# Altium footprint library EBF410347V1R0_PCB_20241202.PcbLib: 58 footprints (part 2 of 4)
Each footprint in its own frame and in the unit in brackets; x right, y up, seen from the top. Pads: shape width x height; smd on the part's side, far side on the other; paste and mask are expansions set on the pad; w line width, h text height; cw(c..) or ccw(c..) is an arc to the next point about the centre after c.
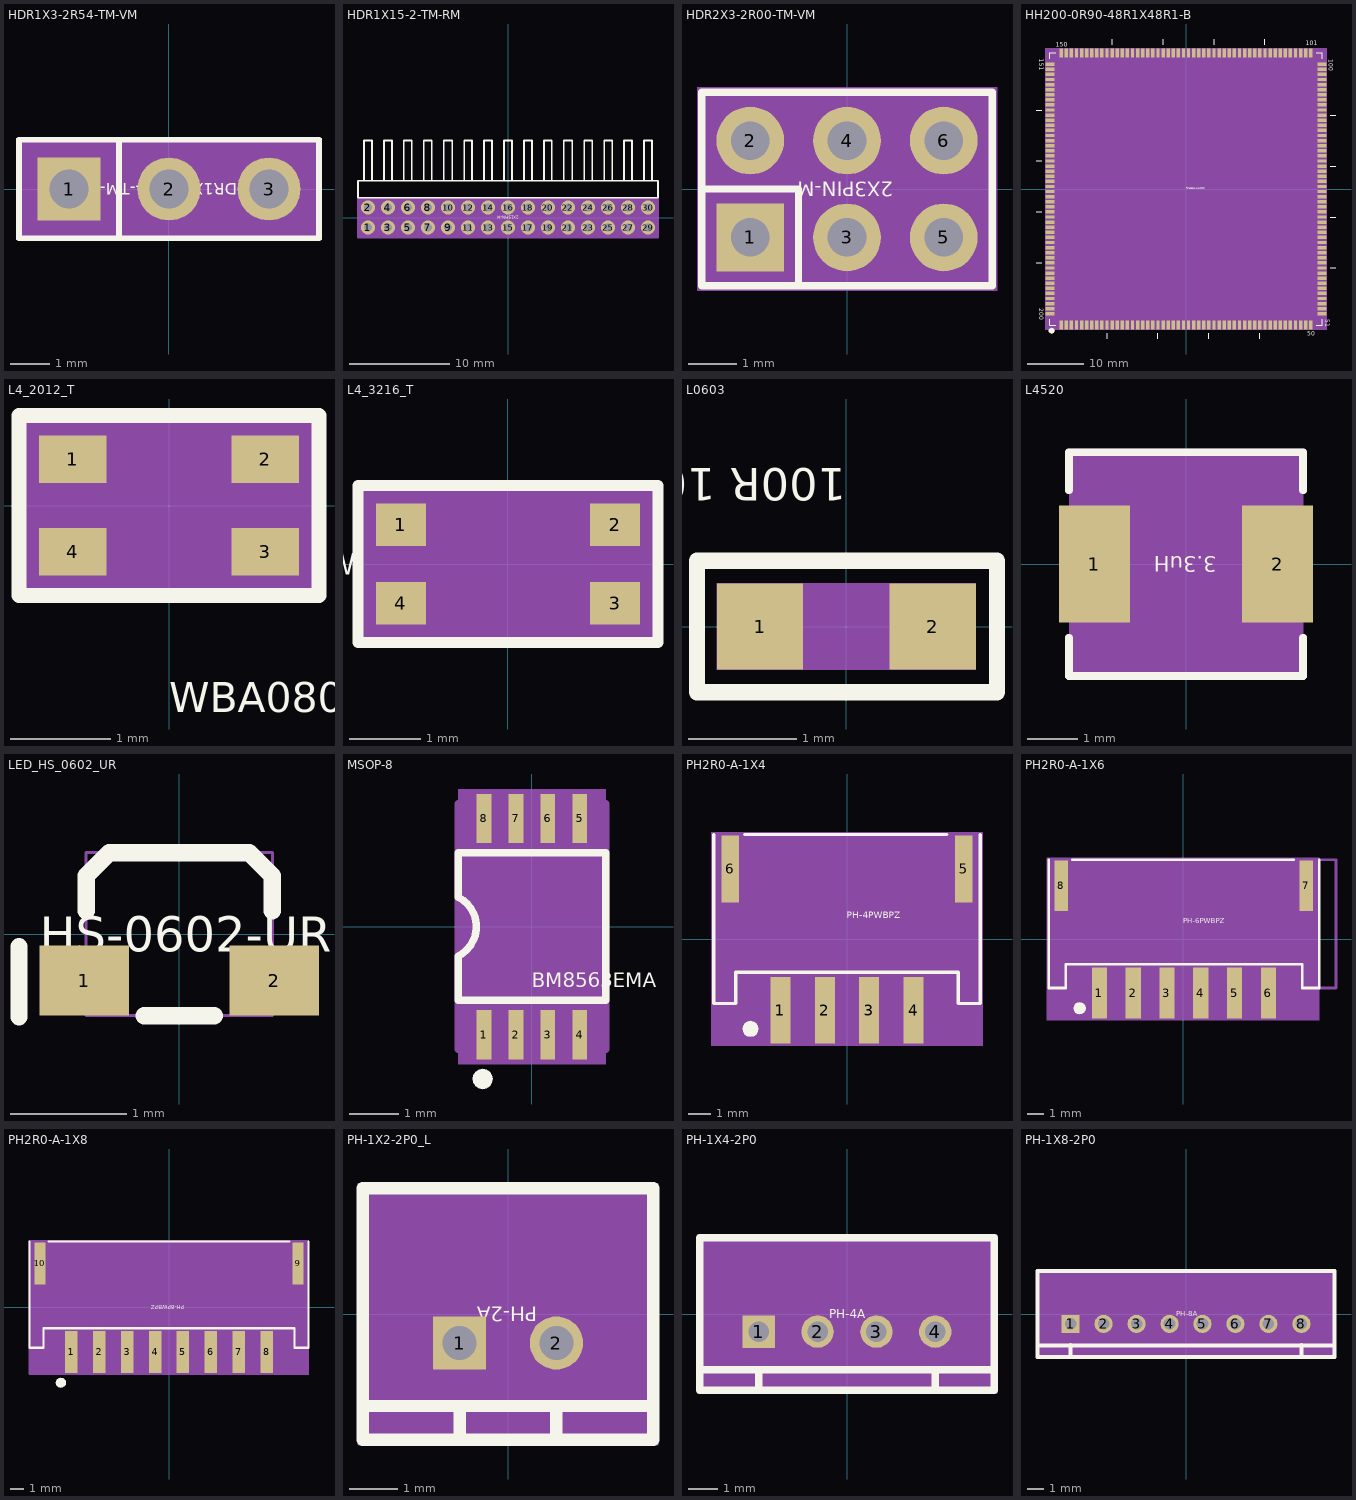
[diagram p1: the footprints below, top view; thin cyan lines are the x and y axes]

## HDR1X3-2R54-TM-VM [mm] "HDR1X3-2R54-TM-VM"
pads (3):
  rect 1.6x1.6 hole 1: 1(-2.535,0)
  round 1.6 hole 1: 2(0.005,0) 3(2.545,0)
Top Overlay:
  lines w0.15: -1.265,-1.25 -1.265,1.25 ; -1.265,1.25 3.815,1.25 3.815,-1.25 -3.805,-1.25 -3.805,1.25 -1.265,1.25
  text "HDR1X3-2R54-TM-VM" at 2.04,0.15 h0.3
Bottom Overlay:
  lines w0.5: -1.265,-0.6 -1.265,0.6 ; 1.275,-0.6 1.275,0.6
Top 3D Body:
  region: -3.805,1.25 -3.805,-1.25 3.805,-1.25 3.805,1.25
Mechanical 14:
  text "3" at 2.799,0 h0.64
  text "2" at 0.259,0 h0.64
  text "1" at -2.281,0 h0.64
Top Assembly:
  lines w0.15: -3.805,-1.25 3.815,-1.25 3.815,1.25 -3.805,1.25 -3.805,-1.25
3D body: height 3.81, standoff 0, extent -3.805,-1.25 3.805,1.25

## HDR1X15-2-TM-RM [mm] "HDR1X15-2-TM-RM"
pads (30):
  round 1.4 hole 0.8: 1(-14,-1) 2(-14,1) 3(-12,-1) 4(-12,1) 5(-10,-1) 6(-10,1) 7(-8,-1) 8(-8,1) 9(-6,-1) 10(-6,1) 11(-4,-1) 12(-4,1) 13(-2,-1) 14(-2,1) 15(0,-1) 16(0,1) 17(2,-1) 18(2,1) 19(4,-1) 20(4,1) 21(6,-1) 22(6,1) 23(8,-1) 24(8,1) 25(10,-1) 26(10,1) 27(12,-1) 28(12,1) 29(14,-1) 30(14,1)
Top Overlay:
  lines w0.15: -14.4,3.7 -14.4,7.7 -13.6,7.7 -13.6,3.7 ; -12.4,3.7 -12.4,7.7 -11.6,7.7 -11.6,3.7 ; -10.4,3.7 -10.4,7.7 -9.6,7.7 -9.6,3.7 ; -8.4,3.7 -8.4,7.7 -7.6,7.7 -7.6,3.7 ; -6.4,3.7 -6.4,7.7 -5.6,7.7 -5.6,3.7 ; -4.4,3.7 -4.4,7.7 -3.6,7.7 -3.6,3.7 ; -2.4,3.7 -2.4,7.7 -1.6,7.7 -1.6,3.7 ; -0.4,3.7 -0.4,7.7 0.4,7.7 0.4,3.7 ; 1.6,3.7 1.6,7.7 2.4,7.7 2.4,3.7 ; 3.6,3.7 3.6,7.7 4.4,7.7 4.4,3.7 ; 5.6,3.7 5.6,7.7 6.4,7.7 6.4,3.7 ; 7.6,3.7 7.6,7.7 8.4,7.7 8.4,3.7 ; 9.6,3.7 9.6,7.7 10.4,7.7 10.4,3.7 ; 11.6,3.7 11.6,7.7 12.4,7.7 12.4,3.7 ; 13.6,3.7 13.6,7.7 14.4,7.7 14.4,3.7 ; -15,2 -15,3.7 15,3.7 15,2 -15,2
  text "2X15PIN-M" at 1.08,0.15 h0.3
Bottom Overlay:
  lines w0.5: -14.6,0 14.6,0 ; -13,-1.5 -13,1.5 ; -11,-1.5 -11,1.5 ; -9,-1.5 -9,1.5 ; -7,-1.5 -7,1.5 ; -5,-1.5 -5,1.5 ; -3,-1.5 -3,1.5 ; -1,-1.5 -1,1.5 ; 1,-1.5 1,1.5 ; 3,-1.5 3,1.5 ; 5,-1.5 5,1.5 ; 7,-1.5 7,1.5 ; 9,-1.5 9,1.5 ; 11,-1.5 11,1.5 ; 13,-1.5 13,1.5
Top 3D Body:
  region: -15,2 -15,-2 15,-2 15,2
Mechanical 14:
  text "5" at -9.746,-1 h0.64
  text "13" at -1.492,-1 h0.64
  text "25" at 10.508,-1 h0.64
  text "4" at -11.746,1 h0.64
  text "6" at -9.746,1 h0.64
  text "14" at -1.492,1 h0.64
  text "26" at 10.508,1 h0.64
  text "23" at 8.508,-1 h0.64
  text "11" at -3.492,-1 h0.64
  text "16" at 0.508,1 h0.64
  text "12" at -3.492,1 h0.64
  text "21" at 6.508,-1 h0.64
  text "9" at -5.746,-1 h0.64
  text "19" at 4.508,-1 h0.64
  text "30" at 14.508,1 h0.64
  text "10" at -5.492,1 h0.64
  text "17" at 2.508,-1 h0.64
  text "1" at -13.746,-1 h0.64
  text "3" at -11.746,-1 h0.64
  text "2" at -13.746,1 h0.64
  text "28" at 12.508,1 h0.64
  text "8" at -7.746,1 h0.64
  text "24" at 8.508,1 h0.64
  text "22" at 6.508,1 h0.64
  text "29" at 14.508,-1 h0.64
  text "7" at -7.746,-1 h0.64
  text "27" at 12.508,-1 h0.64
  text "15" at 0.508,-1 h0.64
  text "18" at 2.508,1 h0.64
  text "20" at 4.508,1 h0.64
Top Assembly:
  lines w0.15: -15,-2 15,-2 15,2 -15,2 -15,-2
3D body: height 3.81, standoff 0, extent -15,-2 15,2

## HDR2X3-2R00-TM-VM [mm] "HDR2X3-2R00-TM-VM"
pads (6):
  rect 1.4x1.4 hole 0.8: 1(-2,-1)
  round 1.4 hole 0.8: 2(-2,1) 3(0,-1) 4(0,1) 5(2,-1) 6(2,1)
Top Overlay:
  lines w0.15: -3,0 -1,0 -1,-2 ; -3,-2 -3,2 3,2 3,-2 -3,-2
  text "2X3PIN-M" at 0.96,0.15 h0.3
Bottom Overlay:
  lines w0.4: -2.55,0 2.55,0 ; -1,-1.55 -1,1.55 ; 1,-1.55 1,1.55
Top 3D Body:
  region: -3.1,2.1 -3.1,-2.1 3.1,-2.1 3.1,2.1
Mechanical 14:
  text "3" at 0.254,-1 h0.64
  text "5" at 2.254,-1 h0.64
  text "1" at -1.746,-1 h0.64
  text "2" at -1.746,1 h0.64
  text "6" at 2.254,1 h0.64
  text "4" at 0.254,1 h0.64
Top Assembly:
  lines w0.15: -3,-2 -3,2 3,2 3,-2 -3,-2
3D body: height 3.81, standoff 0, extent -3.1,-2.1 3.1,2.1

## HH200-0R90-48R1X48R1-B [mm] "HH200-0R90-48R1X48R1-B"
pads (200):
  rect 0.6x1.6 smd: 1(-22.05,-24.05) 2(-21.15,-24.05) 3(-20.25,-24.05) 4(-19.35,-24.05) 5(-18.45,-24.05) 6(-17.55,-24.05) 7(-16.65,-24.05) 8(-15.75,-24.05) 9(-14.85,-24.05) 10(-13.95,-24.05) 11(-13.05,-24.05) 12(-12.15,-24.05) 13(-11.25,-24.05) 14(-10.35,-24.05) 15(-9.45,-24.05) 16(-8.55,-24.05) 17(-7.65,-24.05) 18(-6.75,-24.05) 19(-5.85,-24.05) 20(-4.95,-24.05) 21(-4.05,-24.05) 22(-3.15,-24.05) 23(-2.25,-24.05) 24(-1.35,-24.05) 25(-0.45,-24.05) 26(0.45,-24.05) 27(1.35,-24.05) 28(2.25,-24.05) 29(3.15,-24.05) 30(4.05,-24.05) 31(4.95,-24.05) 32(5.85,-24.05) 33(6.75,-24.05) 34(7.65,-24.05) 35(8.55,-24.05) 36(9.45,-24.05) 37(10.35,-24.05) 38(11.25,-24.05) 39(12.15,-24.05) 40(13.05,-24.05) 41(13.95,-24.05) 42(14.85,-24.05) 43(15.75,-24.05) 44(16.65,-24.05) 45(17.55,-24.05) 46(18.45,-24.05) 47(19.35,-24.05) 48(20.25,-24.05) 49(21.15,-24.05) 50(22.05,-24.05) 101(22.05,24.05) 102(21.15,24.05) 103(20.25,24.05) 104(19.35,24.05) 105(18.45,24.05) 106(17.55,24.05) 107(16.65,24.05) 108(15.75,24.05) 109(14.85,24.05) 110(13.95,24.05) 111(13.05,24.05) 112(12.15,24.05) 113(11.25,24.05) 114(10.35,24.05) 115(9.45,24.05) 116(8.55,24.05) 117(7.65,24.05) 118(6.75,24.05) 119(5.85,24.05) 120(4.95,24.05) 121(4.05,24.05) 122(3.15,24.05) 123(2.25,24.05) 124(1.35,24.05) 125(0.45,24.05) 126(-0.45,24.05) 127(-1.35,24.05) 128(-2.25,24.05) 129(-3.15,24.05) 130(-4.05,24.05) 131(-4.95,24.05) 132(-5.85,24.05) 133(-6.75,24.05) 134(-7.65,24.05) 135(-8.55,24.05) 136(-9.45,24.05) 137(-10.35,24.05) 138(-11.25,24.05) 139(-12.15,24.05) 140(-13.05,24.05) 141(-13.95,24.05) 142(-14.85,24.05) 143(-15.75,24.05) 144(-16.65,24.05) 145(-17.55,24.05) 146(-18.45,24.05) 147(-19.35,24.05) 148(-20.25,24.05) 149(-21.15,24.05) 150(-22.05,24.05)
  rect 1.6x0.6 smd: 51(24.05,-22.05) 52(24.05,-21.15) 53(24.05,-20.25) 54(24.05,-19.35) 55(24.05,-18.45) 56(24.05,-17.55) 57(24.05,-16.65) 58(24.05,-15.75) 59(24.05,-14.85) 60(24.05,-13.95) 61(24.05,-13.05) 62(24.05,-12.15) 63(24.05,-11.25) 64(24.05,-10.35) 65(24.05,-9.45) 66(24.05,-8.55) 67(24.05,-7.65) 68(24.05,-6.75) 69(24.05,-5.85) 70(24.05,-4.95) 71(24.05,-4.05) 72(24.05,-3.15) 73(24.05,-2.25) 74(24.05,-1.35) 75(24.05,-0.45) 76(24.05,0.45) 77(24.05,1.35) 78(24.05,2.25) 79(24.05,3.15) 80(24.05,4.05) 81(24.05,4.95) 82(24.05,5.85) 83(24.05,6.75) 84(24.05,7.65) 85(24.05,8.55) 86(24.05,9.45) 87(24.05,10.35) 88(24.05,11.25) 89(24.05,12.15) 90(24.05,13.05) 91(24.05,13.95) 92(24.05,14.85) 93(24.05,15.75) 94(24.05,16.65) 95(24.05,17.55) 96(24.05,18.45) 97(24.05,19.35) 98(24.05,20.25) 99(24.05,21.15) 100(24.05,22.05) 151(-24.05,22.05) 152(-24.05,21.15) 153(-24.05,20.25) 154(-24.05,19.35) 155(-24.05,18.45) 156(-24.05,17.55) 157(-24.05,16.65) 158(-24.05,15.75) 159(-24.05,14.85) 160(-24.05,13.95) 161(-24.05,13.05) 162(-24.05,12.15) 163(-24.05,11.25) 164(-24.05,10.35) 165(-24.05,9.45) 166(-24.05,8.55) 167(-24.05,7.65) 168(-24.05,6.75) 169(-24.05,5.85) 170(-24.05,4.95) 171(-24.05,4.05) 172(-24.05,3.15) 173(-24.05,2.25) 174(-24.05,1.35) 175(-24.05,0.45) 176(-24.05,-0.45) 177(-24.05,-1.35) 178(-24.05,-2.25) 179(-24.05,-3.15) 180(-24.05,-4.05) 181(-24.05,-4.95) 182(-24.05,-5.85) 183(-24.05,-6.75) 184(-24.05,-7.65) 185(-24.05,-8.55) 186(-24.05,-9.45) 187(-24.05,-10.35) 188(-24.05,-11.25) 189(-24.05,-12.15) 190(-24.05,-13.05) 191(-24.05,-13.95) 192(-24.05,-14.85) 193(-24.05,-15.75) 194(-24.05,-16.65) 195(-24.05,-17.55) 196(-24.05,-18.45) 197(-24.05,-19.35) 198(-24.05,-20.25) 199(-24.05,-21.15) 200(-24.05,-22.05)
Top Overlay:
  dashed: -23.733,-25.561 -23.538,-25.522 -23.373,-25.411 -23.262,-25.246 -23.223,-25.051 -23.262,-24.856 -23.299,-24.8 -23.373,-24.691 -23.538,-24.58 -23.733,-24.541 -23.928,-24.58 -24.093,-24.691 -24.167,-24.8 -24.204,-24.856 -24.243,-25.051 -24.204,-25.246 -24.093,-25.411 -23.928,-25.522
  lines w0.15: -24.05,-23.05 -24.05,-24.05 -23.05,-24.05 ; -24.05,23.05 -24.05,24.05 -23.05,24.05 ; 23.05,-24.05 24.05,-24.05 24.05,-23.05 ; 23.05,24.05 24.05,24.05 24.05,23.05
  lines w0.2: -26.5,-13.05 -25.5,-13.05 ; -26.5,-4.05 -25.5,-4.05 ; -26.5,4.95 -25.5,4.95 ; -26.5,13.95 -25.5,13.95 ; -13.95,-26.5 -13.95,-25.5 ; -13.05,25.5 -13.05,26.5 ; -4.95,-26.5 -4.95,-25.5 ; -4.05,25.5 -4.05,26.5 ; 4.05,-26.5 4.05,-25.5 ; 4.95,25.5 4.95,26.5 ; 13.05,-26.5 13.05,-25.5 ; 13.95,25.5 13.95,26.5 ; 25.5,-13.95 26.5,-13.95 ; 25.5,-4.95 26.5,-4.95 ; 25.5,4.05 26.5,4.05 ; 25.5,13.05 26.5,13.05
  text "200" at -25.968,-21.089 h0.76
  text "151" at -25.968,22.98 h0.76
  text "150" at -22.996,25.165 h0.76
  text "101" at 21.149,25.368 h0.76
  text "100" at 25.238,22.93 h0.76
  text "51" at 24.629,-22.968 h0.76
  text "50" at 21.454,-25.965 h0.76
  text "RK3562-HH200" at 0,0 h0.3
Top 3D Body:
  region: -24.9,-24.9 -24.9,24.9 24.9,24.9 24.9,-24.9
Mechanical 14:
  text "44" at 16.65,-23.89 h0.1
  text "43" at 15.75,-23.89 h0.1
  text "39" at 12.15,-23.89 h0.1
  text "38" at 11.25,-23.89 h0.1
  text "36" at 9.45,-23.89 h0.1
  text "176" at -24.05,-0.33 h0.1
  text "164" at -24.05,10.47 h0.1
  text "111" at 13.05,24.29 h0.1
  text "185" at -24.05,-8.43 h0.1
  text "89" at 24.05,12.31 h0.1
  text "174" at -24.05,1.47 h0.1
  text "88" at 24.05,11.41 h0.1
  text "195" at -24.05,-17.43 h0.1
  text "192" at -24.05,-14.73 h0.1
  text "187" at -24.05,-10.23 h0.1
  text "181" at -24.05,-4.83 h0.1
  text "173" at -24.05,2.37 h0.1
  text "166" at -24.05,8.67 h0.1
  text "163" at -24.05,11.37 h0.1
  text "160" at -24.05,14.07 h0.1
  text "157" at -24.05,16.77 h0.1
  text "154" at -24.05,19.47 h0.1
  text "151" at -24.05,22.17 h0.1
  text "150" at -22.05,24.29 h0.1
  text "147" at -19.35,24.29 h0.1
  text "146" at -18.45,24.29 h0.1
  text "145" at -17.55,24.29 h0.1
  text "136" at -9.45,24.29 h0.1
  text "133" at -6.75,24.29 h0.1
  text "130" at -4.05,24.29 h0.1
  text "125" at 0.45,24.29 h0.1
  text "122" at 3.15,24.29 h0.1
  text "117" at 7.65,24.29 h0.1
  text "114" at 10.35,24.29 h0.1
  text "109" at 14.85,24.29 h0.1
  text "106" at 17.55,24.29 h0.1
  text "101" at 22.05,24.29 h0.1
  text "98" at 24.05,20.41 h0.1
  text "95" at 24.05,17.71 h0.1
  text "92" at 24.05,15.01 h0.1
  text "87" at 24.05,10.51 h0.1
  text "84" at 24.05,7.81 h0.1
  text "75" at 24.05,-0.29 h0.1
  text "53" at 24.05,-20.09 h0.1
  text "50" at 22.05,-23.89 h0.1
  text "37" at 10.35,-23.89 h0.1
  text "29" at 3.15,-23.89 h0.1
  text "24" at -1.35,-23.89 h0.1
  text "20" at -4.95,-23.89 h0.1
  text "17" at -7.65,-23.89 h0.1
  text "14" at -10.35,-23.89 h0.1
  text "10" at -13.95,-23.89 h0.1
  text "6" at -17.55,-23.97 h0.1
  text "4" at -19.35,-23.97 h0.1
  text "3" at -20.25,-23.97 h0.1
  text "183" at -24.05,-6.63 h0.1
  text "52" at 24.05,-20.99 h0.1
  text "199" at -24.05,-21.03 h0.1
  text "58" at 24.05,-15.59 h0.1
  text "188" at -24.05,-11.13 h0.1
  text "57" at 24.05,-16.49 h0.1
  text "143" at -15.75,24.29 h0.1
  text "28" at 2.25,-23.89 h0.1
  text "91" at 24.05,14.11 h0.1
  text "94" at 24.05,16.81 h0.1
  text "90" at 24.05,13.21 h0.1
  text "96" at 24.05,18.61 h0.1
  text "2" at -21.15,-23.97 h0.1
  text "1" at -22.05,-23.97 h0.1
  text "177" at -24.05,-1.23 h0.1
  text "144" at -16.65,24.29 h0.1
  text "186" at -24.05,-9.33 h0.1
  text "128" at -2.25,24.29 h0.1
  text "9" at -14.85,-23.97 h0.1
  text "124" at 1.35,24.29 h0.1
  text "119" at 5.85,24.29 h0.1
  text "34" at 7.65,-23.89 h0.1
  text "180" at -24.05,-3.93 h0.1
  text "139" at -12.15,24.29 h0.1
  text "141" at -13.95,24.29 h0.1
  text "30" at 4.05,-23.89 h0.1
  text "108" at 15.75,24.29 h0.1
  text "162" at -24.05,12.27 h0.1
  text "77" at 24.05,1.51 h0.1
  text "13" at -11.25,-23.89 h0.1
  text "194" at -24.05,-16.53 h0.1
  text "66" at 24.05,-8.39 h0.1
  text "82" at 24.05,6.01 h0.1
  text "65" at 24.05,-9.29 h0.1
  text "116" at 8.55,24.29 h0.1
  text "68" at 24.05,-6.59 h0.1
  text "67" at 24.05,-7.49 h0.1
  text "104" at 19.35,24.29 h0.1
  text "165" at -24.05,9.57 h0.1
  text "93" at 24.05,15.91 h0.1
  text "113" at 11.25,24.29 h0.1
  text "70" at 24.05,-4.79 h0.1
  text "175" at -24.05,0.57 h0.1
  text "69" at 24.05,-5.69 h0.1
  text "191" at -24.05,-13.83 h0.1
  text "72" at 24.05,-2.99 h0.1
  text "153" at -24.05,20.37 h0.1
  text "49" at 21.15,-23.89 h0.1
  text "71" at 24.05,-3.89 h0.1
  text "32" at 5.85,-23.89 h0.1
  text "48" at 20.25,-23.89 h0.1
  text "135" at -8.55,24.29 h0.1
  text "78" at 24.05,2.41 h0.1
  text "110" at 13.95,24.29 h0.1
  text "140" at -13.05,24.29 h0.1
  text "51" at 24.05,-21.89 h0.1
  text "46" at 18.45,-23.89 h0.1
  text "16" at -8.55,-23.89 h0.1
  text "45" at 17.55,-23.89 h0.1
  text "131" at -4.95,24.29 h0.1
  text "11" at -13.05,-23.89 h0.1
  text "102" at 21.15,24.29 h0.1
  text "41" at 13.95,-23.89 h0.1
  text "19" at -5.85,-23.89 h0.1
  text "47" at 19.35,-23.89 h0.1
  text "31" at 4.95,-23.89 h0.1
  text "112" at 12.15,24.29 h0.1
  text "76" at 24.05,0.61 h0.1
  text "134" at -7.65,24.29 h0.1
  text "54" at 24.05,-19.19 h0.1
  text "126" at -0.45,24.29 h0.1
  text "25" at -0.45,-23.89 h0.1
  text "184" at -24.05,-7.53 h0.1
  text "190" at -24.05,-12.93 h0.1
  text "21" at -4.05,-23.89 h0.1
  text "40" at 13.05,-23.89 h0.1
  text "115" at 9.45,24.29 h0.1
  text "83" at 24.05,6.91 h0.1
  text "197" at -24.05,-19.23 h0.1
  text "168" at -24.05,6.87 h0.1
  text "161" at -24.05,13.17 h0.1
  text "81" at 24.05,5.11 h0.1
  text "132" at -5.85,24.29 h0.1
  text "179" at -24.05,-3.03 h0.1
  text "118" at 6.75,24.29 h0.1
  text "156" at -24.05,17.67 h0.1
  text "55" at 24.05,-18.29 h0.1
  text "138" at -11.25,24.29 h0.1
  text "56" at 24.05,-17.39 h0.1
  text "170" at -24.05,5.07 h0.1
  text "60" at 24.05,-13.79 h0.1
  text "8" at -15.75,-23.97 h0.1
  text "142" at -14.85,24.29 h0.1
  text "158" at -24.05,15.87 h0.1
  text "137" at -10.35,24.29 h0.1
  text "59" at 24.05,-14.69 h0.1
  text "12" at -12.15,-23.89 h0.1
  text "193" at -24.05,-15.63 h0.1
  text "64" at 24.05,-10.19 h0.1
  text "63" at 24.05,-11.09 h0.1
  text "120" at 4.95,24.29 h0.1
  text "123" at 2.25,24.29 h0.1
  text "107" at 16.65,24.29 h0.1
  text "129" at -3.15,24.29 h0.1
  text "155" at -24.05,18.57 h0.1
  text "159" at -24.05,14.97 h0.1
  text "103" at 20.25,24.29 h0.1
  text "171" at -24.05,4.17 h0.1
  text "121" at 4.05,24.29 h0.1
  text "105" at 18.45,24.29 h0.1
  text "42" at 14.85,-23.89 h0.1
  text "18" at -6.75,-23.89 h0.1
  text "15" at -9.45,-23.89 h0.1
  text "97" at 24.05,19.51 h0.1
  text "169" at -24.05,5.97 h0.1
  text "79" at 24.05,3.31 h0.1
  text "80" at 24.05,4.21 h0.1
  text "127" at -1.35,24.29 h0.1
  text "167" at -24.05,7.77 h0.1
  text "178" at -24.05,-2.13 h0.1
  text "152" at -24.05,21.27 h0.1
  text "182" at -24.05,-5.73 h0.1
  text "22" at -3.15,-23.89 h0.1
  text "172" at -24.05,3.27 h0.1
  text "189" at -24.05,-12.03 h0.1
  text "7" at -16.65,-23.97 h0.1
  text "23" at -2.25,-23.89 h0.1
  text "27" at 1.35,-23.89 h0.1
  text "26" at 0.45,-23.89 h0.1
  text "149" at -21.15,24.29 h0.1
  text "148" at -20.25,24.29 h0.1
  text "196" at -24.05,-18.33 h0.1
  text "200" at -24.05,-21.93 h0.1
  text "33" at 6.75,-23.89 h0.1
  text "62" at 24.05,-11.99 h0.1
  text "198" at -24.05,-20.13 h0.1
  text "74" at 24.05,-1.19 h0.1
  text "100" at 24.05,22.29 h0.1
  text "35" at 8.55,-23.89 h0.1
  text "99" at 24.05,21.31 h0.1
  text "61" at 24.05,-12.89 h0.1
  text "73" at 24.05,-2.09 h0.1
  text "86" at 24.05,9.61 h0.1
  text "85" at 24.05,8.71 h0.1
  text "5" at -18.45,-23.97 h0.1
Top Assembly:
  lines w0.15: -24.05,-24.05 24.05,-24.05 24.05,24.05 -24.05,24.05 -24.05,-24.05
3D body: height 3.81, standoff 0, extent -24.9,-24.9 24.9,24.9

## L4_2012_T [mm] "L4_2012_T"
pads (4):
  rect 0.675x0.475 smd: 1(-0.963,0.463) 2(0.963,0.463) 3(0.963,-0.463) 4(-0.963,-0.463)
Top Overlay:
  lines w0.15: -1.5,-0.9 -1.5,0.8 -1.5,0.9 1.5,0.9 1.5,-0.9 -1.5,-0.9
  text "WBA0805D801PT-HF" at 0,-2.07 h0.3
Top 3D Body:
  region: -1.5,0.9 -1.5,-0.9 1.5,-0.9 1.5,0.9
Mechanical 14:
  text "1" at -0.963,0.209 h0.64
  text "2" at 0.962,0.209 h0.64
  text "3" at 0.962,-0.716 h0.64
  text "4" at -0.963,-0.716 h0.64
Top Assembly:
  lines w0.15: -1,-0.6 1,-0.6 1,0.6 -1,0.6 -1,-0.6
3D body: height 3.81, standoff 0, extent -1.5,-0.9 1.5,0.9

## L4_3216_T [mm] "L4_3216_T"
pads (4):
  rect 0.7x0.6 smd: 1(-1.5,0.55) 2(1.5,0.55) 3(1.5,-0.55) 4(-1.5,-0.55)
Top Overlay:
  lines w0.15: -2.1,-1.1 -2.1,1.1 2.1,1.1 2.1,-1.1 -2.1,-1.1
  text "WBA3416L600T-D-HF" at -2.04,0.15 h0.3
Top 3D Body:
  region: -2.1,1.1 -2.1,-1.1 2.1,-1.1 2.1,1.1
Mechanical 14:
  text "3" at 1.246,-0.55 h0.64
  text "1" at -1.754,0.55 h0.64
  text "2" at 1.246,0.55 h0.64
  text "4" at -1.754,-0.55 h0.64
Top Assembly:
  lines w0.15: -1.6,-0.8 1.6,-0.8 1.6,0.8 -1.6,0.8 -1.6,-0.8
3D body: height 3.81, standoff 0, extent -2.1,-1.1 2.1,1.1

## L0603 [mil] "L0603"
pads (2):
  rect 31.5x31.5 smd: 1(-31.5,0) 2(31.5,0)
Top Overlay:
  lines w6: -54.5,-24 55,-24 55,24 -54.5,24 -54.5,-24
  text "100R 100MHz" at -0.01,57.87 h11.81
Top 3D Body:
  region: -47.24,-15.75 -47.24,15.75 47.24,15.75 47.24,-15.75
Mechanical 14:
  text "1" at -31.5,14 h35
  text "2" at 31.5,14 h35
3D body: height 150, standoff 0, extent -47.24,-15.75 47.24,15.75

## L4520 [mm] "L4520"
pads (2):
  rect 1.4x2.3 smd: 1(-1.803,-0.002) 2(1.798,-0.002)
Top Overlay:
  lines w0.15: -2.303,-1.452 -2.303,-2.202 2.298,-2.202 2.298,-1.452 ; -2.303,1.447 -2.303,2.198 2.298,2.198 2.298,1.447
  text "3.3uH" at 0.6,0.15 h0.3
Top 3D Body:
  region: -2.303,-2.202 2.303,-2.202 2.303,2.203 -2.303,2.203
Mechanical 14:
  text "2" at 2.052,-0.002 h0.64
  text "1" at -1.549,-0.002 h0.64
Top Assembly:
  lines w0.15: -2.303,-1.452 -2.303,-2.202 2.298,-2.202 2.298,-1.452 ; -2.303,1.447 -2.303,2.198 2.298,2.198 2.298,1.447
3D body: height 3.81, standoff 0, extent -2.303,-2.202 2.303,2.203

## LED_HS_0602_UR [mm] "LED_HS_0602_UR"
pads (2):
  rect 0.77x0.6 smd: 1(-0.815,-0.4) 2(0.815,-0.4)
Top Overlay:
  lines w0.15: -1.376,-0.71 -1.376,-0.11 ; -0.8,0.2 -0.8,0.5 -0.6,0.7 0.6,0.7 0.8,0.5 0.8,0.2 ; -0.3,-0.7 0.3,-0.7
  text "HS-0602-UR" at -1.2,-0.15 h0.3
Top 3D Body:
  lines w0.025: -0.8,-0.7 0.8,-0.7 0.8,0.7 -0.8,0.7 -0.8,-0.7
Mechanical 14:
  text "1" at -1.181,-0.4 h0.91
  text "2" at 0.45,-0.4 h0.91

## MSOP-8 [mm] "MSOP-8"
pads (8):
  rect 0.3x1 smd: 1(-0.975,-2.2) 2(-0.325,-2.2) 3(0.325,-2.2) 4(0.975,-2.2) 5(0.975,2.2) 6(0.325,2.2) 7(-0.325,2.2) 8(-0.975,2.2)
Top Overlay:
  dashed: -1,-2.896 -0.922,-2.912 -0.856,-2.956 -0.812,-3.022 -0.796,-3.1 -0.812,-3.178 -0.826,-3.2 -0.856,-3.244 -0.922,-3.288 -1,-3.304 -1.078,-3.288 -1.144,-3.244 -1.174,-3.2 -1.188,-3.178 -1.204,-3.1 -1.188,-3.022 -1.144,-2.956 -1.078,-2.912
  lines w0.15: -1.5,-1.5 1.5,-1.5 1.5,1.5 -1.5,1.5 -1.5,0.6 cw(c-1.8,0) -1.5,-0.6 -1.5,-1.5
  text "BM8563EMA" at 0,-1.23 h0.3
Top 3D Body:
  region: -1.5,2.8 -1.5,-2.8 1.5,-2.8 1.5,2.8
Mechanical 14:
  text "4" at 1.105,-2.91 h0.76
  text "6" at 0.455,1.49 h0.76
  text "5" at 1.105,1.49 h0.76
  text "1" at -0.845,-2.91 h0.76
  text "3" at 0.455,-2.91 h0.76
  text "8" at -0.845,1.49 h0.76
  text "7" at -0.195,1.49 h0.76
  text "2" at -0.195,-2.91 h0.76
Top Assembly:
  lines w0.15: -1.5,-2.5 1.5,-2.5 1.5,2.5 -1.5,2.5 -1.5,-2.5 ; -1.5,-1.5 1.5,-1.5 1.5,1.5 -1.5,1.5 -1.5,-1.5
3D body: height 3.81, standoff 0, extent -1.5,-2.8 1.5,2.8

## PH2R0-A-1X4 [mm] "PH2R0-A-1X4"
pads (6):
  rect 0.9x3 smd: 1(-3,-3.2) 2(-1,-3.2) 3(1,-3.2) 4(3,-3.2)
  rect 0.8x3 smd: 5(5.25,3.15) 6(-5.25,3.15)
Top Overlay:
  dashed: -4.344,-4.402 -4.207,-4.375 -4.091,-4.298 -4.014,-4.182 -3.987,-4.046 -4.014,-3.909 -4.04,-3.87 -4.091,-3.793 -4.207,-3.716 -4.344,-3.689 -4.48,-3.716 -4.596,-3.793 -4.647,-3.87 -4.673,-3.909 -4.7,-4.046 -4.673,-4.182 -4.596,-4.298 -4.48,-4.375
  lines w0.15: -6,4.7 -6,-2.9 -5,-2.9 -5,-1.5 5,-1.5 5,-2.9 6,-2.9 6,4.7 ; -4.6,4.7 4.5,4.7
  text "PH-4PWBPZ" at 0,0.93 h0.3
Top 3D Body:
  region: -6.1,4.8 -6.1,-4.8 6.1,-4.8 6.1,4.8
Mechanical 14:
  text "6" at -5.25,3.404 h0.64
  text "5" at 5.25,3.404 h0.64
  text "1" at -3,-2.946 h0.64
  text "2" at -1,-2.946 h0.64
  text "4" at 3,-2.946 h0.64
  text "3" at 1,-2.946 h0.64
Top Assembly:
  lines w0.15: -5,-2.9 6,-2.9 6,4.7 -5,4.7 -5,0.6 -5,-2.9
3D body: height 3.81, standoff 0, extent -6.1,-4.8 6.1,4.8

## PH2R0-A-1X6 [mm] "PH2R0-A-1X6"
pads (8):
  rect 0.9x3 smd: 1(-4.95,-3.2) 2(-2.95,-3.2) 3(-0.95,-3.2) 4(1.05,-3.2) 5(3.05,-3.2) 6(5.05,-3.2)
  rect 0.8x3 smd: 7(7.3,3.15) 8(-7.2,3.15)
Top Overlay:
  dashed: -6.118,-4.453 -5.981,-4.426 -5.865,-4.349 -5.788,-4.233 -5.761,-4.096 -5.788,-3.96 -5.814,-3.921 -5.865,-3.844 -5.981,-3.767 -6.118,-3.74 -6.254,-3.767 -6.37,-3.844 -6.422,-3.921 -6.447,-3.96 -6.475,-4.096 -6.447,-4.233 -6.37,-4.349 -6.254,-4.426
  lines w0.15: -7.95,4.7 -7.95,-2.9 -6.95,-2.9 -6.95,-1.5 7.05,-1.5 7.05,-2.9 8.05,-2.9 8.05,4.7 ; -6.55,4.7 6.55,4.7
  text "PH-6PWBPZ" at 0,0.93 h0.3
Top 3D Body:
  region: -8.05,4.8 -8.05,-4.8 8.05,-4.8 8.05,4.8
Mechanical 14:
  text "7" at 7.3,3.404 h0.64
  text "8" at -7.2,3.404 h0.64
  text "1" at -4.95,-2.946 h0.64
  text "5" at 3.05,-2.946 h0.64
  text "4" at 1.05,-2.946 h0.64
  text "2" at -2.95,-2.946 h0.64
  text "3" at -0.95,-2.946 h0.64
  text "6" at 5.05,-2.946 h0.64
Top Assembly:
  lines w0.15: -6.95,-2.9 9.05,-2.9 9.05,4.7 -6.95,4.7 -6.95,0.6 -6.95,-2.9
3D body: height 3.81, standoff 0, extent -8.05,-4.8 8.05,4.8

## PH2R0-A-1X8 [mm] "PH2R0-A-1X8"
pads (10):
  rect 0.9x3 smd: 1(-7,-3.2) 2(-5,-3.2) 3(-3,-3.2) 4(-1,-3.2) 5(1,-3.2) 6(3,-3.2) 7(5,-3.2) 8(7,-3.2)
  rect 0.8x3 smd: 9(9.25,3.15) 10(-9.25,3.15)
Top Overlay:
  dashed: -8.104,-5.407 -8.077,-5.544 -7.999,-5.66 -7.884,-5.737 -7.747,-5.764 -7.61,-5.737 -7.572,-5.711 -7.495,-5.66 -7.417,-5.544 -7.39,-5.407 -7.417,-5.271 -7.495,-5.155 -7.572,-5.103 -7.61,-5.078 -7.747,-5.05 -7.884,-5.078 -7.999,-5.155 -8.077,-5.271
  lines w0.15: -10,4.7 -10,-2.9 -9,-2.9 -9,-1.5 9,-1.5 9,-2.9 10,-2.9 10,4.7 ; -8.64,4.7 8.64,4.7
  text "PH-8PWBPZ" at 1.08,0.15 h0.3
Top 3D Body:
  region: -10,4.8 -10,-4.8 10,-4.8 10,4.8
Mechanical 14:
  text "9" at 9.504,3.15 h0.64
  text "8" at 7.254,-3.2 h0.64
  text "10" at -8.742,3.15 h0.64
  text "7" at 5.254,-3.2 h0.64
  text "6" at 3.254,-3.2 h0.64
  text "5" at 1.254,-3.2 h0.64
  text "4" at -0.746,-3.2 h0.64
  text "3" at -2.746,-3.2 h0.64
  text "2" at -4.746,-3.2 h0.64
  text "1" at -6.746,-3.2 h0.64
Top Assembly:
  lines w0.025: -10,-4.8 -10,4.8 10,4.8 10,-4.8 -10,-4.8
3D body: height 3.81, standoff 0, extent -10,-4.8 10,4.8

## PH-1X2-2P0_L [mm] "PH-1X2-2P0_L"
pads (2):
  rect 1.1x1.1 hole 0.7: 1(-1,-0.6)
  round 1.1 hole 0.7: 2(1,-0.6)
Top Overlay:
  lines w0.254: -3,-1.9 3,-1.9 ; -1,-2.6 -1,-1.9 ; 1,-2.6 1,-1.9 ; -3,-2.6 -3,2.6 3,2.6 3,-2.6 -3,-2.6
  text "PH-2A" at 0.6,0.15 h0.3
Bottom Overlay:
  lines w0.6: 0,-1.1 0,-0.1
Top 3D Body:
  region: -3.1,2.7 -3.1,-2.7 3.1,-2.7 3.1,2.7
Mechanical 14:
  text "1" at -0.746,-0.6 h0.64
  text "2" at 1.254,-0.6 h0.64
Top Assembly:
  lines w0.025: -3.1,-2.7 -3.1,2.7 3.1,2.7 3.1,-2.7 -3.1,-2.7
3D body: height 3.81, standoff 0, extent -3.1,-2.7 3.1,2.7

## PH-1X4-2P0 [mm] "PH-1X4-2P0"
pads (4):
  rect 1.1x1.1 hole 0.7: 1(-3,-0.6)
  round 1.1 hole 0.7: 2(-1,-0.6) 3(1,-0.6) 4(3,-0.6)
Top Overlay:
  lines w0.254: -5,-1.9 5,-1.9 ; -3,-2.6 -3,-1.9 ; 3,-2.6 3,-1.9 ; -5,-2.6 -5,2.6 5,2.6 5,-2.6 -5,-2.6
  text "PH-4A" at -0.6,-0.15 h0.3
Bottom Overlay:
  lines w0.5: -2,-1.5 -2,0.3 ; 0,-1.5 0,0.3 ; 2,-1.5 2,0.3 ; -3.9,-1.5 -3.9,0.3 3.9,0.3 3.9,-1.5 -3.6,-1.5 -3.9,-1.5
Top 3D Body:
  region: -5.1,2.7 -5.1,-2.7 5.1,-2.7 5.1,2.7
Mechanical 14:
  text "4" at 2.644,-0.6 h0.89
  text "1" at -3.356,-0.6 h0.89
  text "3" at 0.644,-0.6 h0.89
  text "2" at -1.356,-0.6 h0.89
3D body: height 3.81, standoff 0, extent -5.1,-2.7 5.1,2.7

## PH-1X8-2P0 [mm] "PH-1X8-2P0"
pads (8):
  rect 1.1x1.1 hole 0.7: 1(-7,-0.6)
  round 1.1 hole 0.7: 2(-5,-0.6) 3(-3,-0.6) 4(-1,-0.6) 5(1,-0.6) 6(3,-0.6) 7(5,-0.6) 8(7,-0.6)
Top Overlay:
  lines w0.25: -9,-2.6 9,-2.6 ; -9,-1.9 7,-1.9 9,-1.9 ; -9,2.6 9,2.6
  lines w0.254: -9,-2.6 -9,2.6 ; -7,-2.6 -7,-1.9 ; 7,-2.6 7,-1.9 ; 9,-2.6 9,2.6
  text "PH-8A" at -0.6,-0.15 h0.3
Bottom Overlay:
  lines w0.4: -6,-1 -6,-0.2 ; -4,-1 -4,-0.2 ; -2,-1 -2,-0.2 ; 0,-1 0,-0.2 ; 2,-1 2,-0.2 ; 4,-1 4,-0.2 ; 6,-1 6,-0.2
Top 3D Body:
  region: -9.1,2.7 -9.1,-2.7 9.1,-2.7 9.1,2.7
Mechanical 14:
  text "7" at 4.624,-0.6 h0.94
  text "8" at 6.624,-0.6 h0.94
  text "1" at -7.376,-0.6 h0.94
  text "5" at 0.624,-0.6 h0.94
  text "3" at -3.376,-0.6 h0.94
  text "6" at 2.624,-0.6 h0.94
  text "2" at -5.376,-0.6 h0.94
  text "4" at -1.376,-0.6 h0.94
3D body: height 3.81, standoff 0, extent -9.1,-2.7 9.1,2.7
